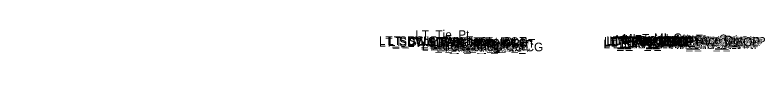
# Model space of a CAD drawing. Extents: x 0 to 4229, y -1 to 9523.
# Drawn here: x 3000 to 3171.5, y 4500 to 4508.6 of the extents above; entities that cross this region are included whole.
import ezdxf

# ---------------------------------------------------------------- set-up
doc = ezdxf.new("R2010")
doc.units = 0
doc.layers.add('Default', color=7, linetype='Continuous')

msp = doc.modelspace()

# ---------------------------------------------------------------- texts
at = {"layer": 'Default'}
for s, height, p in [('LT_Tie_Pt', 2, (3091.58, 4506.48)), ('LT_SDWK_Out_Top', 2, (3083.24, 4505.07)), ('LT_SDWK_Out_Bot', 2, (3083.27, 4504.74)), ('LT_CSLP_Pnt', 2, (3085.17, 4505.1)), ('LT_Sub_Trench_Out_DLT', 2, (3085.49, 4504.9)), ('LT_SDWK_In_Top', 2, (3089.86, 4504.97)), ('LT_SDWK_In_Bot', 2, (3089.89, 4504.64)), ('LT_CG_Top_Face', 2, (3094.76, 4504.86)), ('LT_CG_Top_BOC', 2, (3095.28, 4504.86)), ('LT_PV1_OEOT', 2, (3100.24, 4504.48)), ('LT_PV2_OEEOP', 2, (3134.69, 4504.94)), ('LT_PV3_OEEOP', 2, (3134.69, 4504.69)), ('LT_PV1_OEEOP', 2, (3135.26, 4505.07)), ('LT_PV2_IEEOP', 2, (3135.34, 4504.94)), ('LT_PV1_IEEOP', 2, (3135.91, 4505.07)), ('LT_PV2_PGL1', 2, (3136.27, 4504.94)), ('LT_PV3_PGL1', 2, (3136.27, 4504.69)), ('LT_PV2_PGL', 2, (3136.6, 4504.94)), ('LT_PV1_PGL', 2, (3137.17, 4505.19)), ('MI_Face In', 2, (3137.29, 4505.36)), ('MI_Bot In', 2, (3138.27, 4505.19)), ('MI_Top In', 2, (3139, 4505.61)), ('MI_Crown', 2, (3146.14, 4505.75)), ('RT_PV2_OEEOP', 2, (3150.01, 4504.82)), ('RT_PV3_OEEOP', 2, (3150.01, 4504.57)), ('RT_PV1_OEEOP', 2, (3150.58, 4504.95)), ('RT_PV2_IEEOP', 2, (3150.66, 4504.82)), ('MI_Face Out', 2, (3151.01, 4505.24)), ('MI_Top Out', 2, (3151.22, 4505.49)), ('RT_PV1_IEEOP', 2, (3151.22, 4504.95)), ('RT_PV2_PGL1', 2, (3151.58, 4504.82)), ('RT_PV3_PGL1', 2, (3151.58, 4504.57)), ('RT_PV2_PGL', 2, (3151.92, 4504.82)), ('MI_Bot Out', 2, (3152.01, 4505.07)), ('RT_PV1_PGL', 2, (3152.48, 4505.07)), ('LT_CG1_Shelf_Out', 2, (3093.05, 4503.83)), ('LT_CG_Bot_BOC', 2, (3095.31, 4503.84)), ('LT_CG_Top_Gut', 2, (3095.74, 4504.36)), ('LT_Sub_OEOP', 2, (3096.36, 4503.58)), ('LT_Sub_OEOT_CG', 2, (3096.87, 4503.64)), ('LT_CG_Bot_IE', 2, (3099.41, 4503.89)), ('LT_Sub_OEOT', 2, (3099.58, 4503.6)), ('LT_PV2_OEOT', 2, (3099.67, 4504.23)), ('LT_PV3_OEOT', 2, (3099.67, 4503.98)), ('LT_Sub_OEEOP', 2, (3134.6, 4504.32)), ('LT_PV4_PGL', 2, (3136.6, 4504.32)), ('RT_Sub_OEEOP', 2, (3149.92, 4504.2)), ('RT_PV4_PGL', 2, (3151.92, 4504.2)), ('-', 0.0001, (3000, 4500)), ('-', 0.0001, (3000, 4500)), ('-', 0.0001, (3000, 4500)), ('-', 0.0001, (3000, 4500)), ('-', 0.0001, (3000, 4500)), ('-', 0.0001, (3000, 4500)), ('-', 0.0001, (3000, 4500))]:
    msp.add_text(s, height=height, dxfattribs=at).set_placement(p)

doc.saveas('drawing.dxf')
